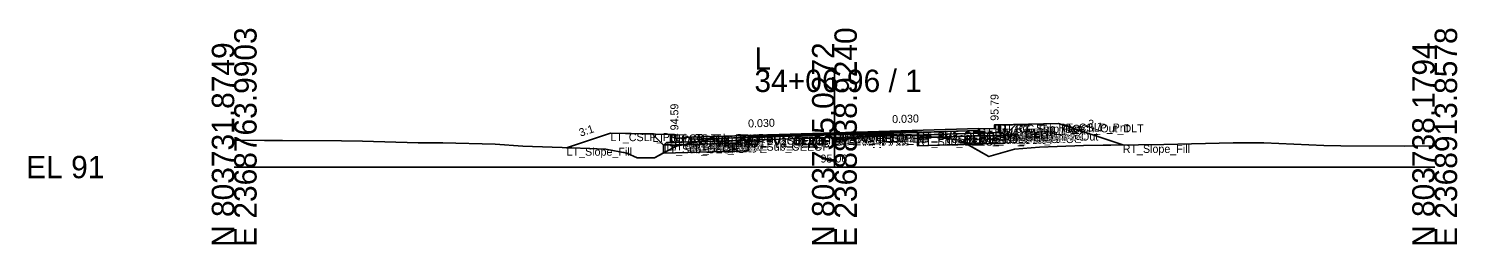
# Model space of a CAD drawing. Extents: x -26 to 8153, y -10 to 9520.
# Drawn here: x 1974.3 to 2152.8, y 8990.3 to 9017.3 of the extents above; entities that cross this region are included whole.
import ezdxf

# ---------------------------------------------------------------- set-up
doc = ezdxf.new("R2010")
doc.units = 0
for name, color, linetype in [('Exist CMT Pavement', 7, 'Continuous'), ('Exist Cross Section Cell', 7, 'Continuous'), ('Exist XS Center Line Elevation Label', 7, 'Continuous'), ('Exist XS Ground Line', 7, 'Continuous'), ('Prop CMT Conc Surface', 7, 'Continuous'), ('Prop CMT Concrete Structures', 7, 'Continuous'), ('Prop CMT Pvmt Course 1', 7, 'Continuous'), ('Prop CMT Pvmt Course 1 CG', 7, 'Continuous'), ('Prop CMT Pvmt Course 1 Wedge', 7, 'Continuous'), ('Prop CMT Pvmt Course 2', 7, 'Continuous'), ('Prop CMT Pvmt Course 2 Wedge', 7, 'Continuous'), ('Prop CMT Pvmt Course 3', 7, 'Continuous'), ('Prop CMT Pvmt Course 3 Wedge', 7, 'Continuous'), ('Prop CMT Pvmt Surface', 7, 'Continuous'), ('Prop CMT Pvmt Wedge Surface 1', 7, 'Continuous'), ('Prop CMT Pvmt Wedge Surface 2', 7, 'Continuous'), ('Prop CMT Pvmt Wedge Surface 3', 7, 'Continuous'), ('Prop CMT Shallow Undercut', 7, 'Continuous'), ('Prop CMT Shallow Undercut Boundary', 7, 'Continuous'), ('Prop CMT Slope Grass', 7, 'Continuous'), ('Prop CMT Subgrade Earthwork', 7, 'Continuous'), ('Prop XS Earthwork Shape', 7, 'Continuous'), ('Prop XS Hydro Elevations', 7, 'Continuous'), ('Prop XS SE Text', 7, 'Continuous'), ('Prop XS Side Slope Text', 7, 'Continuous'), ('Prop XS Subgrade Earthwork', 7, 'Continuous'), ('Scratch_Level_2', 7, 'Continuous'), ('Scratch_Level_6', 7, 'Continuous')]:
    doc.layers.add(name, color=color, linetype=linetype)

msp = doc.modelspace()

# ---------------------------------------------------------------- linework, layer by layer
at = {"layer": 'Exist CMT Pavement'}
for p, q in [((2064.21, 9003.8), (2065.59, 9003.83)), ((2065.59, 9003.83), (2065.95, 9003.86)), ((2065.95, 9003.86), (2074.59, 9004.06)), ((2074.59, 9004.06), (2075, 9004.06)), ((2075, 9004.06), (2081.17, 9004.01)), ((2081.17, 9004.01), (2085.36, 9003.98))]:
    msp.add_line(p, q, dxfattribs=at)
at = {"layer": 'Exist Cross Section Cell'}
for p, q in [((2075, 9000), (2075, 9012.19)), ((2000, 9000), (2075, 9000)), ((2075, 9000), (2150, 9000))]:
    msp.add_line(p, q, dxfattribs=at)
at = {"layer": 'Exist XS Ground Line'}
for p, q in [((2057.37, 9003.06), (2059.29, 9003.45)), ((2059.29, 9003.45), (2063.03, 9003.71)), ((2063.03, 9003.71), (2064.21, 9003.8)), ((2064.21, 9003.8), (2065.59, 9003.83)), ((2065.59, 9003.83), (2065.95, 9003.86)), ((2065.95, 9003.86), (2074.59, 9004.06)), ((2074.59, 9004.06), (2075, 9004.06)), ((2075, 9004.06), (2081.17, 9004.01)), ((2081.17, 9004.01), (2085.36, 9003.98)), ((2085.36, 9003.98), (2090.67, 9003.37)), ((2000, 9003.35), (2003.78, 9003.33)), ((2003.78, 9003.33), (2006.04, 9003.33)), ((2006.04, 9003.33), (2013.39, 9003.27)), ((2013.39, 9003.27), (2016.05, 9003.25)), ((2016.05, 9003.25), (2022.99, 9003.02)), ((2022.99, 9003.02), (2026.06, 9003.02)), ((2026.06, 9003.02), (2032.6, 9002.86)), ((2032.6, 9002.86), (2036.06, 9002.61)), ((2036.06, 9002.61), (2042.2, 9002.4)), ((2042.2, 9002.4), (2046.45, 9002.23)), ((2046.45, 9002.23), (2049.05, 9001.75)), ((2049.05, 9001.75), (2050.37, 9001.14)), ((2052.51, 9001.15), (2054.15, 9002.03)), ((2054.15, 9002.03), (2054.92, 9002.45)), ((2054.92, 9002.45), (2055.27, 9002.62)), ((2055.27, 9002.62), (2055.68, 9002.71)), ((2055.68, 9002.71), (2057.37, 9003.06)), ((2090.67, 9003.37), (2094.31, 9001.3)), ((2094.31, 9001.3), (2097.51, 9002.25)), ((2097.51, 9002.25), (2100.63, 9002.49)), ((2100.63, 9002.49), (2102.84, 9002.59)), ((2102.84, 9002.59), (2106.13, 9002.69)), ((2106.13, 9002.69), (2112.98, 9002.8)), ((2112.98, 9002.8), (2116.14, 9002.81)), ((2116.14, 9002.81), (2124.82, 9003.04)), ((2124.82, 9003.04), (2126.15, 9003.03)), ((2126.15, 9003.03), (2128.65, 9003.02)), ((2128.65, 9003.02), (2136.16, 9002.68)), ((2136.16, 9002.68), (2138.26, 9002.66)), ((2138.26, 9002.66), (2146.17, 9002.62)), ((2146.17, 9002.62), (2150, 9002.64)), ((2050.37, 9001.14), (2052.51, 9001.15))]:
    msp.add_line(p, q, dxfattribs=at)
at = {"layer": 'Prop CMT Conc Surface'}
for points in [[(2095, 9004.79), (2095, 9005.29), (2095.5, 9005.29)], [(2055, 9003.59), (2055, 9004.09), (2054.5, 9004.09)], [(2057, 9003.73), (2055, 9003.59)], [(2093, 9004.81), (2095, 9004.79)]]:
    msp.add_lwpolyline(points, dxfattribs=at)
at = {"layer": 'Prop CMT Concrete Structures'}
for points in [[(2093, 9004.81), (2095, 9004.79), (2095, 9005.29), (2095.5, 9005.29)], [(2095.5, 9005.29), (2095.5, 9004.31), (2093, 9004.23)], [(2057, 9003.73), (2055, 9003.59), (2055, 9004.09), (2054.5, 9004.09)], [(2054.5, 9004.09), (2054.5, 9003.08), (2057, 9003.15)], [(2057, 9003.15), (2057, 9003.73)], [(2093, 9004.23), (2093, 9004.81)]]:
    msp.add_lwpolyline(points, dxfattribs=at)
at = {"layer": 'Prop CMT Pvmt Course 1'}
for points in [[(2075, 9004.27), (2057, 9003.73)], [(2057, 9003.73), (2057, 9003.48)], [(2057, 9003.48), (2064.21, 9003.7)], [(2064.21, 9003.82), (2075, 9004.15)], [(2064.21, 9003.7), (2064.21, 9003.82)], [(2075, 9004.27), (2093, 9004.81)], [(2085.36, 9004.46), (2075, 9004.15)], [(2075, 9004.02), (2075, 9004.27)], [(2075, 9004.02), (2075, 9004.27)], [(2075, 9004.15), (2075, 9004.02), (2075, 9004.02)], [(2075, 9004.15), (2075, 9004.02), (2075, 9004.02)], [(2093, 9004.56), (2085.36, 9004.33)], [(2085.36, 9004.33), (2085.36, 9004.46)], [(2093, 9004.81), (2093, 9004.56)]]:
    msp.add_lwpolyline(points, dxfattribs=at)
at = {"layer": 'Prop CMT Pvmt Course 1 CG'}
for points in [[(2093, 9004.23), (2096, 9004.32), (2096.32, 9004)], [(2093, 9003.9), (2093, 9004.23)], [(2096.32, 9004), (2093, 9003.9)], [(2057, 9003.15), (2054, 9003.06), (2053.66, 9002.72)], [(2053.66, 9002.72), (2057, 9002.82)], [(2057, 9002.82), (2057, 9003.15)]]:
    msp.add_lwpolyline(points, dxfattribs=at)
at = {"layer": 'Prop CMT Pvmt Course 1 Wedge'}
for points in [[(2075, 9004.15), (2064.21, 9003.82)], [(2075, 9004.15), (2085.36, 9004.46)]]:
    msp.add_lwpolyline(points, dxfattribs=at)
at = {"layer": 'Prop CMT Pvmt Course 2'}
for points in [[(2064.21, 9003.7), (2057, 9003.48)], [(2057, 9003.48), (2057, 9003.15)], [(2064.21, 9003.37), (2064.21, 9003.7)], [(2085.36, 9004.33), (2093, 9004.56)], [(2085.36, 9004), (2085.36, 9004.33)], [(2093, 9004.23), (2085.36, 9004)], [(2093, 9004.56), (2093, 9004.23)], [(2057, 9003.15), (2064.21, 9003.37)]]:
    msp.add_lwpolyline(points, dxfattribs=at)
at = {"layer": 'Prop CMT Pvmt Course 2 Wedge'}
for points in [[(2075, 9004.02), (2064.21, 9003.7)], [(2075, 9004.02), (2085.36, 9004.33)]]:
    msp.add_lwpolyline(points, dxfattribs=at)
at = {"layer": 'Prop CMT Pvmt Course 3'}
for points in [[(2085.36, 9004), (2093, 9004.23)], [(2085.36, 9003.67), (2085.36, 9004)], [(2093, 9003.9), (2085.36, 9003.67)], [(2093, 9004.23), (2093, 9003.9)], [(2064.21, 9003.37), (2057, 9003.15)], [(2057, 9003.15), (2057, 9002.82)], [(2057, 9002.82), (2064.21, 9003.04)], [(2064.21, 9003.04), (2064.21, 9003.37)]]:
    msp.add_lwpolyline(points, dxfattribs=at)
at = {"layer": 'Prop CMT Pvmt Course 3 Wedge'}
for points in [[(2075, 9003.69), (2064.21, 9003.37)], [(2075, 9003.69), (2085.36, 9004)]]:
    msp.add_lwpolyline(points, dxfattribs=at)
at = {"layer": 'Prop CMT Pvmt Surface'}
for points in [[(2075, 9004.27), (2057, 9003.73)], [(2075, 9004.27), (2093, 9004.81)]]:
    msp.add_lwpolyline(points, dxfattribs=at)
at = {"layer": 'Prop CMT Pvmt Wedge Surface 1'}
for points in [[(2057, 9003.48), (2057, 9003.73)], [(2064.21, 9003.7), (2057, 9003.48)], [(2075, 9004.15), (2064.21, 9003.82)], [(2064.21, 9003.82), (2064.21, 9003.7)], [(2075, 9004.15), (2085.36, 9004.46)], [(2085.36, 9004.33), (2093, 9004.56)], [(2085.36, 9004.46), (2085.36, 9004.33)], [(2093, 9004.56), (2093, 9004.81)]]:
    msp.add_lwpolyline(points, dxfattribs=at)
at = {"layer": 'Prop CMT Pvmt Wedge Surface 2'}
for points in [[(2075, 9004.02), (2057, 9003.48)], [(2057, 9003.48), (2057, 9003.73)], [(2075, 9004.02), (2093, 9004.56)], [(2093, 9004.56), (2093, 9004.81)]]:
    msp.add_lwpolyline(points, dxfattribs=at)
at = {"layer": 'Prop CMT Pvmt Wedge Surface 3'}
for points in [[(2057, 9003.15), (2057, 9003.73)], [(2075, 9003.69), (2057, 9003.15)], [(2075, 9003.69), (2093, 9004.23)], [(2093, 9004.23), (2093, 9004.81)]]:
    msp.add_lwpolyline(points, dxfattribs=at)
at = {"layer": 'Prop CMT Shallow Undercut'}
for points in [[(2087.49, 9003.74), (2090.67, 9003.37), (2091.57, 9002.86), (2085.36, 9002.67), (2085.36, 9003.67)], [(2053.66, 9001.72), (2064.21, 9002.04), (2064.21, 9003.04), (2056.08, 9002.79), (2055.68, 9002.71), (2055.27, 9002.62), (2054.92, 9002.45), (2054.15, 9002.03), (2053.66, 9001.77)]]:
    msp.add_lwpolyline(points, close=True, dxfattribs=at)
at = {"layer": 'Prop CMT Shallow Undercut Boundary'}
for p, q in [((2085.36, 9003.67), (2096.32, 9004)), ((2085.36, 9003.67), (2085.36, 9002.67)), ((2096.32, 9004), (2096.32, 9003)), ((2053.66, 9002.72), (2064.21, 9003.04)), ((2053.66, 9002.72), (2053.66, 9001.72)), ((2053.66, 9001.72), (2064.21, 9002.04)), ((2064.21, 9003.04), (2064.21, 9002.04)), ((2085.36, 9002.67), (2096.32, 9003))]:
    msp.add_line(p, q, dxfattribs=at)
at = {"layer": 'Prop CMT Slope Grass'}
for points in [[(2095.5, 9005.29), (2103, 9005.44), (2111.02, 9002.77)], [(2054.5, 9004.09), (2047, 9004.24), (2041.53, 9002.42)]]:
    msp.add_lwpolyline(points, dxfattribs=at)
at = {"layer": 'Prop CMT Subgrade Earthwork'}
for points in [[(2093, 9003.9), (2096.32, 9004), (2097.66, 9005.34)], [(2057, 9002.82), (2053.66, 9002.72), (2052.24, 9004.14)], [(2064.21, 9003.04), (2064.22, 9003.8)], [(2085.36, 9003.67), (2085.35, 9003.98)], [(2085.36, 9003.67), (2093, 9003.9)], [(2064.21, 9003.04), (2057, 9002.82)]]:
    msp.add_lwpolyline(points, dxfattribs=at)
at = {"layer": 'Prop XS Earthwork Shape'}
for points in [[(2091.57, 9002.86), (2094.31, 9001.3), (2097.51, 9002.25), (2100.63, 9002.49), (2102.84, 9002.59), (2106.13, 9002.69), (2111.02, 9002.77), (2103, 9005.44), (2097.66, 9005.34), (2096.32, 9004), (2096.32, 9003)], [(2047, 9004.24), (2041.53, 9002.42), (2042.2, 9002.4), (2046.45, 9002.23), (2049.05, 9001.75), (2050.37, 9001.14), (2052.51, 9001.15), (2053.66, 9001.77), (2053.66, 9002.72), (2052.24, 9004.14)], [(2064.21, 9003.04), (2057, 9002.82), (2056.08, 9002.79), (2057.37, 9003.06), (2059.29, 9003.45), (2063.03, 9003.71), (2064.21, 9003.8), (2064.22, 9003.8)], [(2085.36, 9003.67), (2087.49, 9003.74), (2085.36, 9003.98), (2085.35, 9003.98)], [(2085.36, 9003.67), (2087.49, 9003.74), (2090.67, 9003.37), (2091.57, 9002.86), (2085.36, 9002.67)], [(2093, 9003.9), (2096.32, 9004), (2096.32, 9003), (2091.57, 9002.86), (2090.67, 9003.37), (2087.49, 9003.74)], [(2053.66, 9001.77), (2054.15, 9002.03), (2054.92, 9002.45), (2055.27, 9002.62), (2055.68, 9002.71), (2056.08, 9002.79), (2057, 9002.82), (2064.21, 9003.04), (2064.21, 9002.04), (2053.66, 9001.72)], [(2053.66, 9001.77), (2054.15, 9002.03), (2054.92, 9002.45), (2055.27, 9002.62), (2055.68, 9002.71), (2056.08, 9002.79), (2053.66, 9002.72)]]:
    msp.add_lwpolyline(points, close=True, dxfattribs=at)
at = {"layer": 'Prop XS Subgrade Earthwork'}
for p, q in [((2085.36, 9003.67), (2096.32, 9004)), ((2053.66, 9002.72), (2064.21, 9003.04))]:
    msp.add_line(p, q, dxfattribs=at)
at = {"layer": 'Scratch_Level_6'}
for points in [[(2087.49, 9003.74), (2090.67, 9003.37), (2091.57, 9002.86), (2085.36, 9002.67), (2085.36, 9003.67)], [(2053.66, 9001.72), (2064.21, 9002.04), (2064.21, 9003.04), (2056.08, 9002.79), (2055.68, 9002.71), (2055.27, 9002.62), (2054.92, 9002.45), (2054.15, 9002.03), (2053.66, 9001.77)]]:
    msp.add_lwpolyline(points, close=True, dxfattribs=at)

# ---------------------------------------------------------------- texts
at = {"layer": 'Exist Cross Section Cell'}
for s, p in [('E 2368763.9903', (2002.8, 8990)), ('E 2368838.9240', (2077.8, 8990)), ('E 2368913.8578', (2152.8, 8990)), ('N 803731.8749', (2000, 8990)), ('N 803735.0272', (2075, 8990)), ('N 803738.1794', (2150, 8990))]:
    msp.add_text(s, height=2.8, rotation=90, dxfattribs=at).set_placement(p)
for s, p in [('L', (2065, 9012.19)), ('34+06.96 / 1', (2065, 9009.39)), ('EL 91', (1974, 8998.6))]:
    msp.add_text(s, height=2.8, dxfattribs=at).set_placement(p)
at = {"layer": 'Exist XS Center Line Elevation Label'}
msp.add_text('95.06', height=1, dxfattribs=at).set_placement((2073.26, 9000.56))
at = {"layer": 'Prop XS Hydro Elevations'}
for s, p in [('95.79', (2095.5, 9005.79)), ('94.59', (2055.5, 9004.59))]:
    msp.add_text(s, height=1, rotation=90, dxfattribs=at).set_placement(p)
at = {"layer": 'Prop XS SE Text'}
for p in [(2064.22, 9004.95), (2082.22, 9005.49)]:
    msp.add_text('0.030', height=1, rotation=1.7184, dxfattribs=at).set_placement(p)
at = {"layer": 'Prop XS Side Slope Text'}
for rotation, p in [(18.4349, (2043.28, 9003.79)), (341.5651, (2106.49, 9005.07))]:
    msp.add_text('3:1', height=1, rotation=rotation, dxfattribs=at).set_placement(p)
at = {"layer": 'Scratch_Level_2'}
for s, p in [('RT_CG_Top_Face', (2095, 9004.29)), ('RT_CG_Top_BOC', (2095.5, 9004.29)), ('RT_Sub_Trench_Out_DLT', (2097.66, 9004.34)), ('RT_CSLP_Pnt', (2103, 9004.44)), ('LT_CSLP_Pnt', (2047, 9003.24)), ('LT_Sub_Trench_Out_DLT', (2052.24, 9003.14)), ('LT_CG_Top_BOC', (2054.5, 9003.09)), ('LT_CG_Top_Face', (2055, 9003.09)), ('LT_CG_Top_Gut', (2055, 9002.59)), ('LT_PV1_OEOT', (2057, 9002.73)), ('LT_PV2_OEOT', (2057, 9002.48)), ('LT_PV1_OEEOP', (2064.21, 9002.82)), ('LT_PV_OEEOP_EG', (2064.21, 9002.8)), ('LT_PV2_OEEOP', (2064.21, 9002.7)), ('LT_PV_Sub_Tie_Out', (2064.22, 9002.8)), ('PV1_PGL', (2075, 9003.27)), ('RT_PV1_IEEOP', (2075, 9003.15)), ('LT_PV1_IEEOP', (2075, 9003.15)), ('RT_PV_IEEOP_EG', (2075, 9003.06)), ('LT_PV_IEEOP_EG', (2075, 9003.06)), ('RT_PV2_IEEOP', (2075, 9003.02)), ('LT_PV2_IEEOP', (2075, 9003.02)), ('PV2_PGL', (2075, 9003.02)), ('RT_PV3_IEEOP', (2075, 9002.69)), ('LT_PV3_IEEOP', (2075, 9002.69)), ('RT_PV_Sub_Tie_Out', (2085.35, 9002.98)), ('RT_PV1_OEEOP', (2085.36, 9003.46)), ('RT_PV2_OEEOP', (2085.36, 9003.33)), ('RT_PV3_OEEOP', (2085.36, 9003)), ('RT_PV_OEEOP_EG', (2085.36, 9002.98)), ('RT_Sub_OEEOP', (2085.36, 9002.67)), ('RT_PV1_OEOT', (2093, 9003.81)), ('RT_PV2_OEOT', (2093, 9003.56)), ('RT_PV3_OEOT', (2093, 9003.23)), ('RT_CG_Bot_IE', (2093, 9003.23)), ('RT_Sub_OEOT', (2093, 9002.9)), ('RT_CG_Top_Gut', (2095, 9003.79)), ('RT_CG_Bot_BOC', (2095.5, 9003.31)), ('RT_CG1_Shelf_Out', (2096, 9003.32)), ('RT_Sub_OEOP', (2096.32, 9003)), ('LT_Slope_Fill', (2041.53, 9001.42)), ('LT_Sub_OEOP', (2053.66, 9001.72)), ('LT_CG1_Shelf_Out', (2054, 9002.06)), ('LT_CG_Bot_BOC', (2054.5, 9002.08)), ('LT_PV3_OEOT', (2057, 9002.15)), ('LT_CG_Bot_IE', (2057, 9002.15)), ('LT_Sub_OEOT', (2057, 9001.82)), ('LT_PV3_OEEOP', (2064.21, 9002.37)), ('LT_Sub_OEEOP', (2064.21, 9002.04)), ('RT_Slope_Fill', (2111.02, 9001.77))]:
    msp.add_text(s, height=1, dxfattribs=at).set_placement(p)

doc.saveas('drawing.dxf')
